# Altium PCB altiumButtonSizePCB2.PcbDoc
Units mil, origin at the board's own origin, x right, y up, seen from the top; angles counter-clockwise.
Board outline 1649.61 x 824.8 mil, 2 copper layers (Top Layer, Bottom Layer); 34 components, 33 nets, 168 pads, 45 vias.
Unrouted connection lines stored in the file: 1.
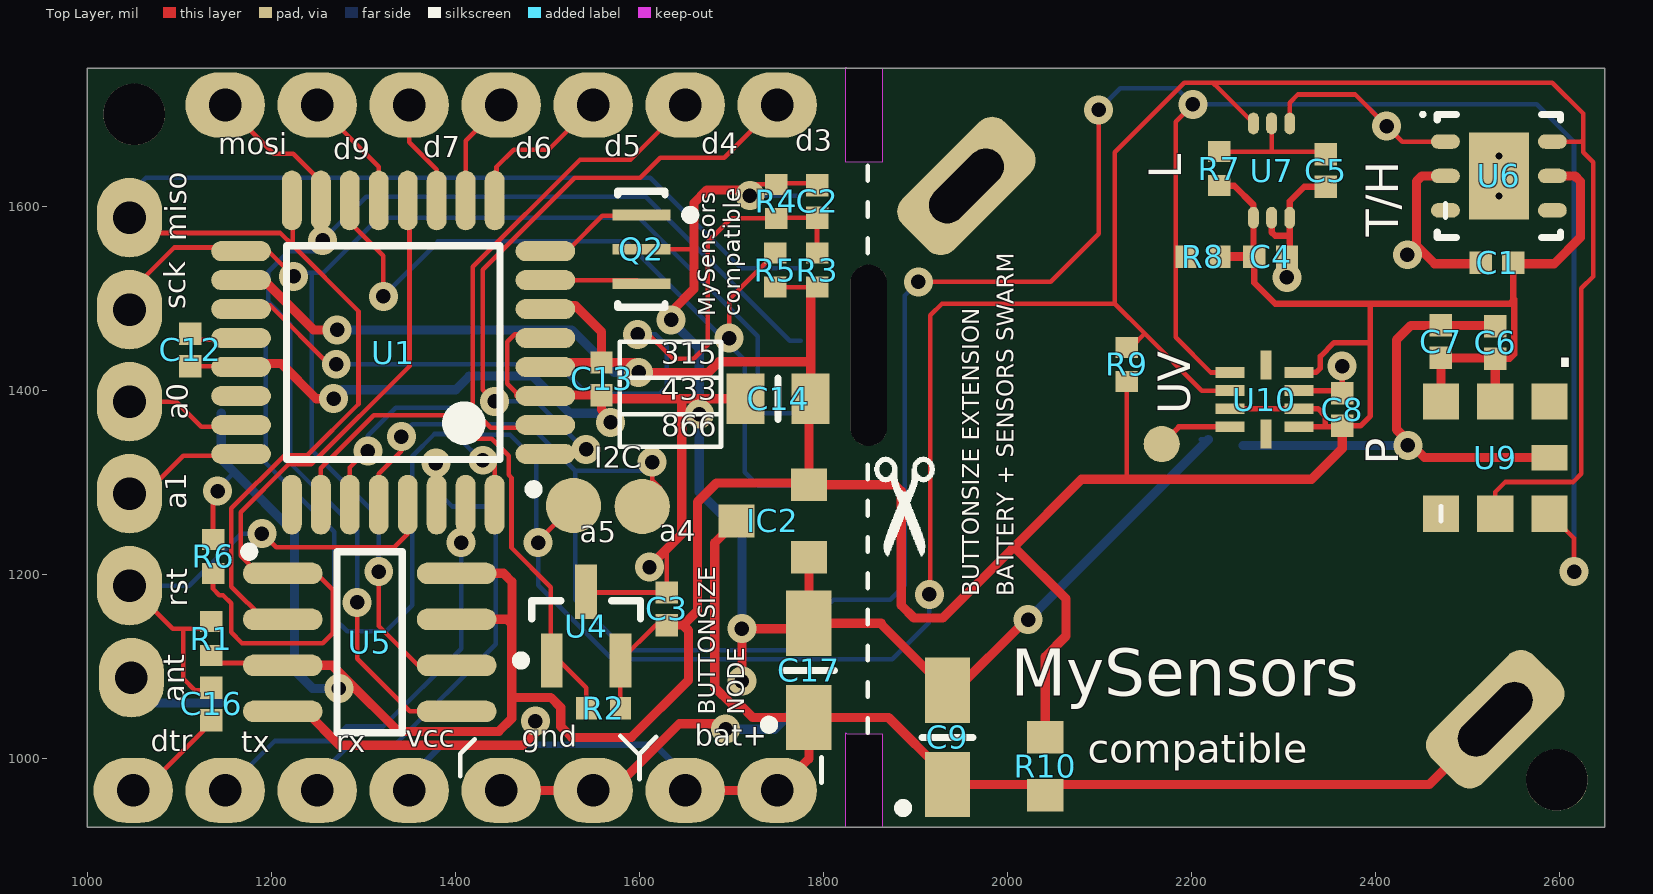
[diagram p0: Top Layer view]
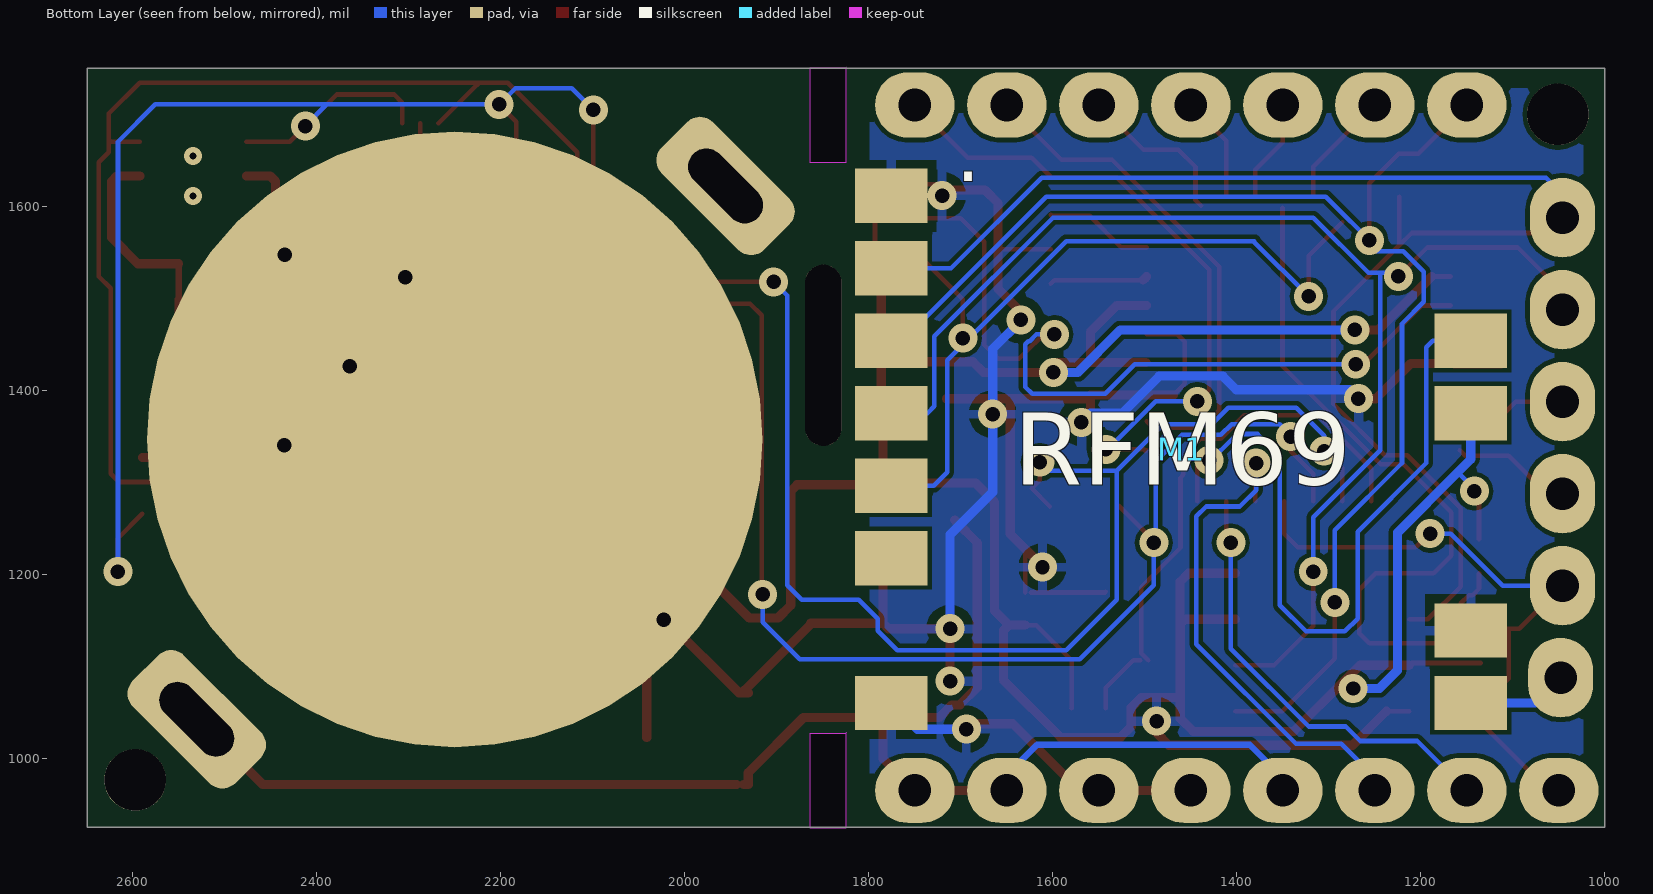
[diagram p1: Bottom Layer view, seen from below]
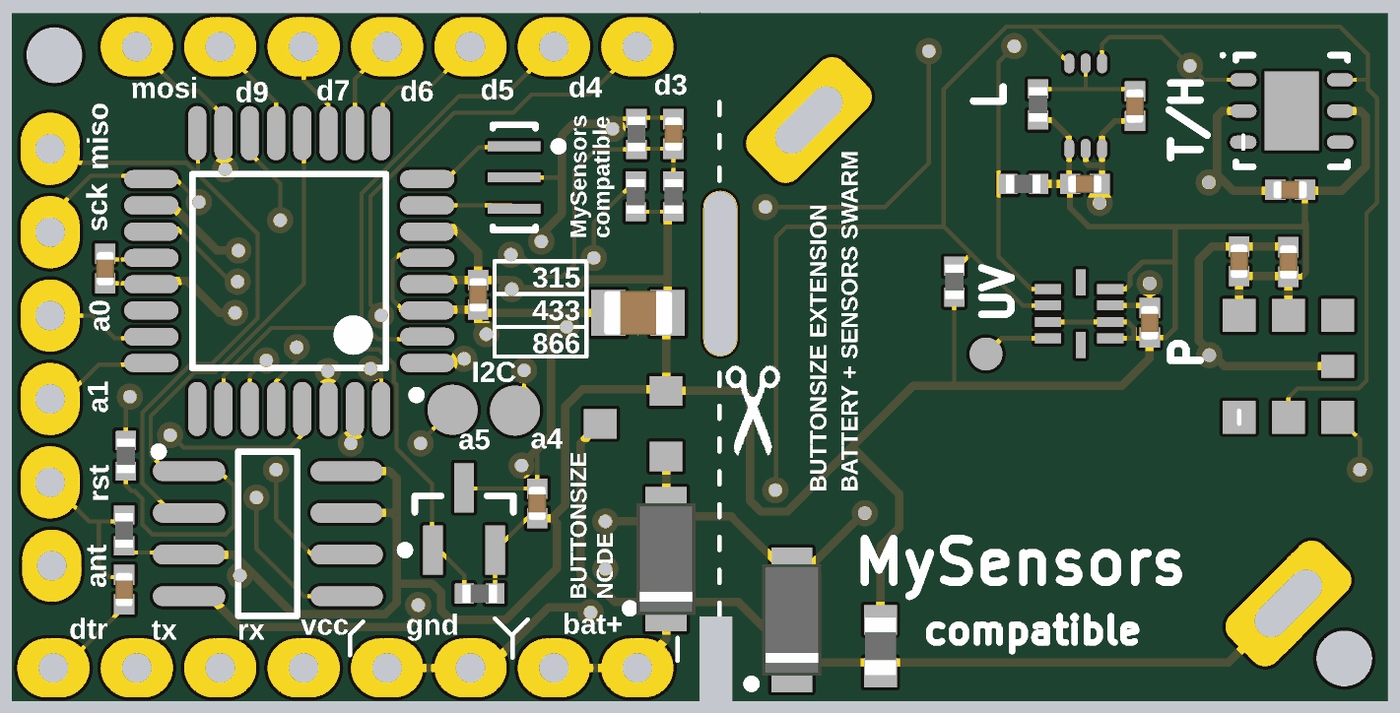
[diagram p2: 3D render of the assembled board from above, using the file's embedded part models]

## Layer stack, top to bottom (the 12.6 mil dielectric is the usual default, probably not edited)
Top Solder: solder mask 0.4, Solder Resist, Dk 3.5
Top Layer: signal copper 1.4
Dielectric 1: dielectric 12.6, FR-4, Dk 4.8
Bottom Layer: signal copper 1.4
Bottom Solder: solder mask 0.4, Solder Resist, Dk 3.5

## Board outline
1000,925.2 2649.61,925.2 2649.61,1750 1000,1750
cut-out: 1824.8,924.21 1824.8,1027.56 1825.79,1026.57 1864.17,1026.57 1864.17,924.21
cut-out: 1824.8,1647.64 1824.8,1750.98 1825.79,1750 1864.17,1750 1864.17,1647.64

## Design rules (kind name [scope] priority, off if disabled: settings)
Clearance [All] p1: gap=5
PolygonConnect [All] p1: connectstyle=Relief reliefconductorwidth=10 reliefentries=4 polygonreliefangle="90 Angle" airgapwidth=10
RoutingVias [All] p1: holewidth=15.75 width=31.5 viastyle="Through Hole" minholewidth=15.75 minwidth=31.5 maxholewidth=39.37 maxwidth=50
ShortCircuit ShortCircuit_1 [InNet('BAT+') vs InNet('VDD1')] p1: allowed=TRUE
ShortCircuit [All] p2: allowed=FALSE
SolderMaskExpansion [All] p1: expansion=4
Width [All] p1: maxlimit=10 minlimit=5 preferedwidth=5
29 further rules are at their usual default settings.

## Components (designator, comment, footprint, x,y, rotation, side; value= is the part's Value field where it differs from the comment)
C1 "100nF" CAPC1005X55N 2532.48,1538.39 r0 top
C2 "100nF" CAPC1005X55N 1793.31,1605.31 r270 top
C3 "100nF" CAPC1005X55N 1629.92,1162.4 r90 top
C4 "100nF" CAPC1005X55N 2286.42,1545.28 r180 top
C5 "100nF" CAPC1005X55N 2346.46,1638.78 r90 top
C6 "100nF" CAPC1005X55N 2530.51,1451.77 r90 top
C7 "100nF" CAPC1005X55N 2471.46,1452.76 r90 top
C8 "100nF" CAPC1005X55N 2364.17,1378.94 r270 top
C9 "47uF" CAPMP3216X180N 1935.04,1022.64 r90 top
C12 "100nF" CAPC1005X55N 1112.2,1443.9 r90 top
C13 "100nF" CAPC1005X55N 1559.06,1412.4 r90 top
C14 "4.7uF" CAPC2012X135N 1750.98,1390.75 r0 top
C16 "100nF" CAPC1005X55N 1134.84,1059.06 r270 top
C17 "47uF" CAPMP3216X180N 1784.45,1095.47 r90 top
IC2 "xc6206p332mr" XC6206 1784.45,1297.24 r270 top
M1 "rfm69hcw" rf69_rev3.0 1421.26,1335.63 r180 bottom
Q2 "CSTCE16M0V51-R0" MURA-CSTCE_V-3_V 1602.36,1553.15 r270 top
R1 "10k" RESC1005X40N 1134.84,1129.92 r90 top
R2 "100k" RESC1005X40N 1561.02,1054.13 r180 top
R3 "1M" RESC1005X40N 1793.31,1530.51 r270 top
R4 "470k" RESC1005X40N 1749.02,1605.31 r270 top
R5 "10k" RESC1005X40N 1748.03,1530.51 r270 top
R6 "10k" RESC1005X40N 1136.81,1219.49 r270 top
R7 "10k" RESC1005X40N 2230.32,1640.75 r270 top
R8 "1k" RESC1005X40N 2212.6,1545.28 r180 top
R9 "1k" RESC1005X40N 2129.92,1428.15 r90 top
R10 "0" RESC1608X55N 2041.34,991.14 r90 top
U1 "ATmega328P-AU" 32A_N 1352.36,1440.94 r180 top
U4 "ATSHA204A" 3TS1_N 1542.32,1143.7 r90 top
U5 "M25P40-VMN6TPB" MICT-MN-8_N 1307.09,1125.98 r0 top
U6 "si7020" DFN6D_N 2534.45,1632.87 r0 top
U7 "bh1750" BH1750 2287.4,1638.78 r0 top
U9 "BMP180" BMP180 2530.51,1326.77 r0 top
U10 "si1132" si1132 2281.5,1379.92 r0 top

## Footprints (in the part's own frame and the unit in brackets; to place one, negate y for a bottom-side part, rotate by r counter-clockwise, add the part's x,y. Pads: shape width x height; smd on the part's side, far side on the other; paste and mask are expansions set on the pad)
3TS1_N [mm] "SOT23, 3-Leads, Body 2.9x1.3mm, Pitch 0.95mm, Lead Span 2.4mm, IPC Medium Density"
  rect 1.5x0.6 smd: 1(-0.95,0.95) 2(-0.95,-0.95) 3(0.95,0)
  silkscreen extent -1.07,-1.5 0.7,1.92, body extent -0.7,-1.52 0.7,1.52, height 1.12
32A_N [mm] "Thin QFP, 32-Leads, Body 7x7mm, Pitch 0.8mm, IPC Medium Density"
  oval 1.65x0.55 smd: 1(-3.7,2.8) 2(-3.7,2) 3(-3.7,1.2) 4(-3.7,0.4) 5(-3.7,-0.4) 6(-3.7,-1.2) 7(-3.7,-2) 8(-3.7,-2.8) 17(4.7,-2.8) 18(4.7,-2) 19(4.7,-1.2) 20(4.7,-0.4) 21(4.7,0.4) 22(4.7,1.2) 23(4.7,2) 24(4.7,2.8)
  oval 0.55x1.65 smd: 9(-2.3,-4.2) 10(-1.5,-4.2) 11(-0.7,-4.2) 12(0.1,-4.2) 13(0.9,-4.2) 14(1.7,-4.2) 15(2.5,-4.2) 16(3.3,-4.2) 25(3.3,4.2) 26(2.5,4.2) 27(1.7,4.2) 28(0.9,4.2) 29(0.1,4.2) 30(-0.7,4.2) 31(-1.5,4.2) 32(-2.3,4.2)
  silkscreen extent -3.5,-2.95 3.45,3.9, body extent -3,-3.5 4,3.5, height 1.2
BH1750 [mm]
  oval 0.3x0.6 smd: 1(-0.5,-1.3) 2(0,-1.3) 3(0.5,-1.3) 4(0.5,1.3) 5(0,1.3) 6(-0.5,1.3)
  body extent -0.8,-1.2 0.8,1.2, height 0.75
BMP180 [mm]
  rect 1x1 smd: 1(1.5,1.55) 2(0,1.55) 3(-1.5,1.55) 4(-1.5,-1.55) 5(0,-1.55) 6(1.5,-1.55)
  rect 1x0.7 smd: 7(1.5,0)
  body extent -1.96,-1.86 1.96,1.86, height 0.93
CAPC1005X55N [mm] "Chip Capacitor, Body 1.0x0.55mm, IPC Medium Density"
  rect 0.62x0.62 smd: 1(-0.45,0) 2(0.45,0)
  body extent -0.52,-0.27 0.53,0.28, height 0.55
CAPC2012X135N [mm] "Chip Capacitor, Body 2.0x1.25mm, IPC Medium Density"
  rect 1.05x1.4 smd: 1(-0.9,0) 2(0.9,0)
  silkscreen extent 0,-0.58 0,0.58, body extent -1.05,-0.67 1.05,0.68, height 1.25
CAPMP3216X180N [mm] "Capacitor, Polarized, Molded  Body 3.2x1.6mm, IPC Medium Density"
  rect 1.8x1.25 smd: 1(-1.3,0) 2(1.3,0)
  silkscreen extent -2.07,-0.7 0,1.35, body extent -1.7,-0.9 1.7,0.9, height 1.6
DFN6D_N [mm] "SON, 6-Leads, Body 3x3mm, Pitch 0.95mm, Thermal Pad 2.4x1.65mm, IPC Medium Density"
  oval 0.8x0.4 smd: 1(-1.475,0.95) 2(-1.475,0) 3(-1.475,-0.95) 4(1.475,-0.95) 5(1.475,0) 6(1.475,0.95)
  rect 1.65x2.4 smd: 7(0,0)
  silkscreen extent -2.15,-1.7 1.7,1.75, body extent -1.55,-1.55 1.55,1.55, height 0.95
MICT-MN-8_N [mm] "SOIC, 8-Leads, Body 5x4mm, Pitch 1.27mm, IPC Medium Density"
  oval 2.2x0.6 smd: 1(-2.4,1.905) 2(-2.4,0.635) 3(-2.4,-0.635) 4(-2.4,-1.905) 5(2.4,-1.905) 6(2.4,-0.635) 7(2.4,0.635) 8(2.4,1.905)
  silkscreen extent -3.45,-2.5 0.9,2.62, body extent -2,-2.5 2,2.5, height 0.1
MURA-CSTCE_V-3_V [mm] "SMD, 3-Leads, Body 3.2x1.3mm, Pitch 0.95mm"
  rect 0.3x1.6 smd: 1(-0.95,0) 2(0,0) 3(0.95,0)
  silkscreen extent -1.6,-0.65 1.6,1.48, body extent -1.6,-0.65 1.6,0.65, height 1
RESC1005X40N [mm] "Chip Resistor, EIA 0402, Metric 1005, Body 1.0x0.5mm, IPC Medium Density"
  rect 0.58x0.62 smd: 1(-0.47,0) 2(0.47,0)
  body extent -0.52,-0.27 0.53,0.28, height 0.4
RESC1608X55N [mm] "Chip Resistor, EIA 0603, Metric 1608, Body 1.6x0.8mm, IPC Medium Density"
  rect 0.9x1 smd: 1(-0.8,0) 2(0.8,0)
  body extent -0.87,-0.47 0.88,0.48, height 0.55
rf69_rev3.0 [mm]
  rect 2x1.5 smd: 1(-9,7) 2(-9,5) 3(-9,3) 4(-9,1) 5(-9,-1) 6(-9,-3) 8(-9,-7) 9(7,-7) 10(7,-5) 13(7,1) 14(7,3)
  body extent -8.5,-7.8 6.5,7.8, height 1
si1132 [mm]
  rect 0.8x0.3 smd: 1(-1,1) 2(-1,0.5) 3(-1,0) 4(-1,-0.5) 6(0.9,-0.5) 7(0.9,0) 8(0.9,0.5) 9(0.9,1)
  rect 0.3x0.8 smd: 5(0,-0.7) 10(0,1.2)
  body extent -1.09,-0.81 1.04,1.31, height 0.65
XC6206 [mm]
  rect 0.9x1 smd: 1(1,-2) 2(2,0) 3(0,0)
  body extent -0.5,-1.75 2.5,-0.25, height 1

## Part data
C1 C2 C3 C4 C5 C6 C7 C8 C12 C13 C16: library part CC0402_100NF_16V_10%_X5R, "Non-polarised capacitor"
C9 C17: library part CTE3216-18_10UF_16V_20%_AVX_TCJ, "Polarised capacitor"
C14: library part CC0805_4.7UF_10V_10%_X5R, "Non-polarised capacitor"
IC2: library part XC6206
M1: library part rf69_rev_3.0, "rf69_rev_3.0 16mmx16mm"
Q2: library part CMP-0588-00001-1, "Ceramic Resonator, 8 MHz with Built-in Capacitance, 3.2 x 1.3 x 1 mm SMD, RoHS, Reel"
R1 R5 R6 R7 R8 R9: library part R0402_10K_1%_0.0625W_100PPM, "Resistor - 1%"
R2: library part R0402_4K7_1%_0.0625W_100PPM, "Resistor - 1%"
R3: library part R0402_1M_1%_0.0625W_100PPM, "Resistor - 1%"
R4: library part R0402_470K_1%_0.0625W_100PPM, "Resistor - 1%"
R10: library part R0603_0R_JUMPER, "Resistor"
U1: "8-bit AVR Microcontroller, 32KB Flash, 1KB EEPROM, 2KB SRAM, 32-pin TQFP, Industrial Grade (-40°C to 85°C)"
U4: library part AT88SA10HS-TSU-T, "CryptoAuthentication™ Host Security Chip, Industrial (-40 to 85 degC), 3-Pin SOT, Tape and Reel, Pb-Free"
U5: library part CMP-0357-00076-1, "4 Mb (x1) Serial NOR Flash Memory, 75 MHz, 2.3 to 3.6 V, 8-pin SO8 Narrow (MN), Tape & Reel"

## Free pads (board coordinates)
  oval 70.87x86.61 hole 35.43: 1(1046.06,1187.56) 1(1046.06,1287.56) 1(1046.06,1487.56) 1(1048.03,1087.56) A0(1046.06,1387.56) MISO(1046.06,1587.56)
  oval 86.61x70.87 hole 35.43: 2(1150,1710) 3(1250,1710) 4(1350,1710) 5(1450,1710) 6(1550,1710) 7(1650,1710) 8(1750,1710) 9(1050,965) 9(1150,965) 9(1250,965) 9(1350,965) 9(1450,965) 9(1550,965) 9(1650,965) 9(1750,965)
  round 60 smd: 10(1528.54,1274.61) 11(1603.35,1273.62)
  round 66.93 hole 66.93 unplated: 12(1051.18,1699.8) 12(2597.44,976.38)
  round 669.29 smd far side: 13(2250,1346.46)
  rrect50% 157.48x78.74 hole 39.37 slot 98.43 at 45 deg rot 45: 14(1955.71,1622.05) 14(2530.51,1042.32)
  oval 39.37x196.85 hole 39.37 slot 196.85 at 90 deg: 16(1849.41,1437.99)
  round 39.37 smd: 17(2167.98,1341.54)

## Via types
v1: diameter 31.5, hole 15.75, Top Layer to Bottom Layer, tented both sides, 43 vias
v2: diameter 19.68, hole 7.87, Top Layer to Bottom Layer, tented both sides, 2 vias

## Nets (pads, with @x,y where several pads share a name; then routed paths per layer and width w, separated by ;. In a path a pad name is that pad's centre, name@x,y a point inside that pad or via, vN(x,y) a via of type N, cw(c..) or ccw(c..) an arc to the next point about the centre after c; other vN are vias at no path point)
1132I: pad.17 U10.4 | length 81.9
  Top Layer w6: pad.17 2186.68,1360.24 U10.4
A0: pad.A0 U1.23 | length 125.2
  Top Layer w5: pad.A0 1096.69,1387.56 1124.02,1360.24 1151.57,1360.24 U1.23@1157.48,1366.14
A1: pad.1@1046.06,1287.56 U1.24 | length 130.9
  Top Layer w5: pad.1@1046.06,1287.56 1063.15,1287.56 1104.33,1328.74 1151.57,1328.74 U1.24@1157.48,1334.65
A2: U1.25
A3: R2.2 U1.26 U4.1 | length 599.1
  Top Layer w5: U1.26@1253.94,1279.53 1253.94,1315.36 1311.3,1372.72 1392.04,1372.72 1417.63,1347.13 1439.82,1347.13 1458.05,1328.9 1458.05,1308.02 1461.24,1304.84 1461.24,1228.72 1503.94,1186.02 1503.94,1114.17 U4.1@1496.06,1106.3 ; U4.1 1512.8,1106.3 1542.52,1076.57 R2.2
A4: pad.11 R8.2 U1.27 U6.1 U7.4 U9.6 U10.1 | length 3424.1
  Top Layer w5: U1.27@1285.43,1279.53 1285.43,1315.95 1303.21,1333.73 v1(1305.18,1333.73) ; pad.11 1623.03,1293.31 1614.17,1302.17 v1(1614.17,1321.85) ; v1(1903.54,1517.72) 2047.24,1517.72 2099.41,1569.88 v1(2099.41,1704.72) ; v1(2201.77,1710.63) 2183.07,1691.93 2183.07,1457.68 2221.46,1419.29 U10.1 ; U7.4 2307.09,1712.6 2315.94,1721.46 2378.15,1721.46 v1(2412.52,1687.09) 2429.33,1670.28 U6.1 ; U9.6 2616.14,1239.17 v1(2616.14,1202.76)
  Bottom Layer w5: v1(1305.18,1333.73) 1305.18,1350.46 1335.54,1380.82 1409.54,1380.82 1427.17,1363.19 1479.92,1363.19 1530.66,1312.45 ; v1(1614.17,1321.85) 1614.17,1312.89 1614.61,1312.45 1530.66,1312.45 ; v1(1903.54,1517.72) 1888.78,1502.95 1888.78,1187.99 1873.03,1172.24 1811.02,1172.24 1790.35,1151.57 1790.35,1138.61 1769.24,1117.5 1585.26,1117.5 1530.66,1172.1 1530.66,1312.45 ; v1(2099.41,1704.72) 2123.03,1728.35 2184.06,1728.35 v1(2201.77,1710.63) 2388.98,1710.63 ; v1(2412.52,1687.09) 2388.98,1710.63 ; v1(2616.14,1202.76) 2616.14,1670.28 2575.79,1710.63 2388.98,1710.63
A5: pad.10 R9.2 U1.28 U6.6 U7.6 U9.5 U10.2 | length 3001.3
  Top Layer w5: U1.28@1316.93,1279.53 1316.93,1309.06 1341.6,1333.73 v1(1341.6,1349.48) ; v1(1490.16,1234.25) 1490.16,1236.22 pad.10 ; v1(1915.45,1178.21) 1915.45,1188.09 1916.34,1188.98 1916.34,1481.3 1929.13,1494.09 2117.13,1494.09 ; R9.2 2134.65,1446.65 2149.61,1461.61 ; U10.2 2211.61,1399.61 2149.61,1461.61 ; U7.6 2230.32,1727.36 2223.43,1734.25 ; U9.5 2530.51,1289.37 2541.34,1300.2 2615.16,1300.2 2624.02,1309.06 2624.02,1510.83 2636.81,1523.62 2636.81,1647.64 2625.98,1658.46 2625.98,1672.24 ; U6.6 2624.02,1670.28 2625.98,1672.24 ; 2117.13,1494.09 2149.61,1461.61 ; 2117.13,1494.09 2117.13,1658.86 2192.52,1734.25 2223.43,1734.25 ; 2223.43,1734.25 2592.52,1734.25 2625.98,1700.79 2625.98,1672.24
  Bottom Layer w5: v1(1341.6,1349.48) 1338.58,1346.46 1336.61,1346.46 1353.35,1363.19 1405.51,1363.19 1417.32,1351.38 1459.65,1351.38 1488.19,1322.83 1488.19,1236.22 v1(1490.16,1234.25) 1490.16,1187.99 1570.65,1107.5 1875.22,1107.5 1915.45,1147.73 v1(1915.45,1178.21)
A6: C2.2 R3.1 R4.2 U1.19 | length 959.3
  Top Layer w5: U1.19@1167.32,1492.13 1198.82,1492.13 1262.73,1428.22 v1(1270.73,1428.22) ; v1(1598.43,1460.63) 1598.43,1462.6 1603.35,1467.52 1636.81,1434.06 1659.45,1434.06 1674.59,1449.19 1674.59,1561.4 1700,1586.81 R4.2 ; R4.2@1757.87,1587.8 1758.07,1587.6 C2.2 R3.1
  Bottom Layer w5: v1(1270.73,1428.22) 1510.76,1428.22 1542.93,1396.04 1622.42,1396.04 1629.92,1403.54 1629.92,1449.8 1626.59,1453.13 1625.21,1453.13 1617.71,1460.63 v1(1598.43,1460.63)
A7: U1.22
ANT: M1.9 pad.1@1048.03,1087.56 | length 109
  Bottom Layer w10: pad.1@1048.03,1087.56 1075.55,1060.04 M1.9
BAT+: C9.1 C17.1 IC2.1 pad.9@1350,965 pad.9@1650,965 pad.9@1750,965 pad.14@2530.51,1042.32 R10.1 | length 1674.3
  Top Layer w10: pad.9@1650,965 1750,965 1784.45,999.45 C17.1 ; IC2.1@1706.69,1258.86 IC2.1 1682.09,1234.25 1682.09,1076.91 1701.03,1057.97 1709.75,1057.97 1723.43,1044.29 C17.1 ; C9.1@1936.02,971.46 C9.1 1931.1,971.46 1931.1,984.25 1871.06,1044.29 C17.1 ; C9.1@1943.9,971.46 2458.66,971.46 pad.14@2529.53,1042.32
  Bottom Layer w7: pad.9@1350,965 1350,978.94 1385.83,1014.76 1617.13,1014.76 1650,981.89 1650,965 pad.9@1656.5,971.5
D0: pad.9@1250,965 U1.30 | length 555
  Top Layer w5: v1(1378.94,1320.87) 1379.92,1319.88 U1.30@1379.92,1279.53
  Bottom Layer w5: pad.9@1250,965 1250,979.33 1286.42,1015.75 1335.63,1015.75 1443.9,1124.02 1443.9,1262.8 1433.07,1273.62 1396.65,1273.62 1378.94,1291.34 v1(1378.94,1320.87)
D1: pad.9@1150,965 U1.31 | length 494.5
  Top Layer w5: v1(1406.56,1234.31) 1406.56,1236.28 1408.53,1238.25 1411.42,1235.37 U1.31@1411.42,1279.53
  Bottom Layer w5: pad.9@1155.94,965 1150,965 1203.7,1018.7 1265.75,1018.7 1281.5,1034.45 1321.85,1034.45 1406.56,1119.16 v1(1406.56,1234.31)
D2: M1.14 U1.32 | length 802.4
  Top Layer w5: v1(1430.19,1323.88) 1437.1,1323.88 1442.09,1318.9 1442.91,1319.72 U1.32@1442.91,1279.53
  Bottom Layer w5: M1.14 1187.01,1453.74 1193.9,1446.85 1193.9,1320.87 1268.7,1246.06 1268.7,1151.57 1282.48,1137.8 1324.8,1137.8 1353.35,1166.34 1353.35,1328.15 1377.56,1352.36 1399.61,1352.36 v1@1433.07,1318.9 ; v1@1430.19,1321.78 v1(1430.19,1323.88)
D3: pad.8 U1.1 | length 709.1
  Top Layer w5: v1(1442.91,1387.8) 1430.12,1400.59 1430.12,1530.84 1530.19,1630.91 1601.38,1630.91 1623.03,1652.56 1692.56,1652.56 pad.8 ; U1.1@1498.03,1334.65 1499.02,1333.66 1501.05,1335.7 v1(1542.4,1335.7)
  Bottom Layer w5: v1(1442.91,1387.8) 1488.19,1387.8 1540.29,1335.7 v1(1542.4,1335.7)
D4: pad.7 U1.2 | length 548.7
  Top Layer w5: U1.2@1498.03,1366.14 1491.14,1359.25 1438.58,1359.25 1419.29,1378.54 1419.29,1534.15 1535.73,1650.59 1590.59,1650.59 pad.7
D5: pad.6 U1.9 | length 177.8
  Top Layer w5: U1.9@1438.98,1600.39 1444.88,1606.3 1444.88,1642.72 1463.58,1661.42 1501.42,1661.42 pad.6
D6: pad.5 U1.10 | length 115.7
  Top Layer w5: U1.10@1411.42,1610.24 1411.42,1671.26 1450,1709.84 pad.5
D7: pad.4 U1.11 | length 112.2
  Top Layer w5: pad.4 1350,1669.68 1379.92,1639.76 U1.11@1379.92,1610.24
D8: R6.2 U1.12 U5.1 | length 825.8
  Top Layer w5: R6.2 1136.81,1184.06 1143.7,1177.17 1147.64,1177.17 1156.5,1168.31 1156.5,1136.81 1168.31,1125 1255.91,1125 1266.73,1135.83 1266.73,1183.07 1248.82,1200.98 U5.1 1185.83,1200.98 1166.77,1220.04 1166.77,1267.49 1218.79,1319.51 1243.72,1319.51 1350.39,1426.18 U1.12@1350.39,1598.43
D9: pad.3 U1.13 | length 127.5
  Top Layer w5: pad.3 1316.93,1643.07 U1.13@1316.93,1610.24
D10: M1.5 R5.1 U1.14 | length 871.6
  Top Layer w5: U1.14@1285.43,1582.68 1321.85,1546.26 v1(1321.85,1501.97) ; v1(1697.83,1456.69) 1697.83,1498.82 R5.1
  Bottom Layer w5: v1(1321.85,1501.97) 1380.91,1561.02 1380.91,1562.01 1585.19,1562.01 v1@1694.17,1453.03 ; v1(1697.83,1456.69) 1697.83,1449.37 1714.57,1432.64 1714.57,1311.02 1729.33,1296.26 M1.5
DTR: C16.2 pad.9@1050,965 | length 115.2
  Top Layer w5: pad.9@1050,965 1061.46,965 C16.2@1134.84,1038.39
GND: C1.1 C2.1 C3.2 C4.1 C5.1 C6.2 C7.2 C8.1 C9.2 C12.1 C13.1 C14.1 C17.2 IC2.2 M1.1 M1.8 M1.10 pad.9@1450,965 pad.9@1550,965 pad.13 Q2.2 R4.1 U1.3 U1.5 U1.21 U4.3 U5.4 U6.2 U7.2 U7.3 U9.7 U10.8 | length 4500.3
  Top Layer w5: C12.1 1164.37,1426.18 U1.21@1167.32,1429.13 ; U5.4 U5.4@1237.4,1050.98 ; U1.3@1468.9,1394.69 1456.69,1406.89 1456.69,1452.76 1464.57,1460.63 U1.5@1498.03,1460.63 ; U4.3 1543.31,1180.12 C3.2@1624.02,1180.12 ; pad.9@1550,965 pad.9@1571.3,965 ; C13.1 C13.1@1562.99,1390.75 ; v1(1568.9,1365.16) v1@1568.9,1369.09 ; Q2.2 1658.46,1553.15 1659.45,1554.13 ; v1(1611.22,1207.68) v1@1611.22,1208.66 ; C3.2 1629.92,1227.36 ; v1(1634.84,1476.38) v1@1634.84,1485.38 ; 1645.67,1390.75 1646.28,1390.14 ; v1(1665.35,1374.02) 1665.35,1390.75 ; v1(1720.28,1611.42) 1720.28,1623.82 R4.1 ; R4.1@1749.02,1624.8 C2.1@1791.54,1624.8
  Top Layer w6: U10.8 2361.22,1399.61 C8.1 v1(2364.17,1426.18)
  Top Layer w7: U7.2 2287.4,1571.85 2291.34,1567.91 2307.09,1567.91 ; C4.1@2307.09,1548.23 2307.09,1567.91 ; C5.1 2322.83,1621.06 2307.09,1605.32 U7.3 2307.09,1567.91
  Top Layer w10: U1.21@1167.32,1429.13 1210.63,1429.13 1248.95,1390.82 v1(1267.78,1390.82) ; U5.4@1237.4,1050.98 1274.21,1014.17 1473.82,1014.17 1487.28,1027.63 v1(1487.28,1040.41) ; pad.9@1450,965 pad.9@1550,965 ; U1.3@1468.9,1394.69 C13.1 1559.06,1378.94 v1@1568.9,1369.09 ; C13.1@1562.99,1390.75 1645.67,1390.75 1665.35,1390.75 C14.1 ; pad.9@1571.3,965 1643.7,1037.4 1688.13,1037.4 v1(1693.98,1031.55) ; v1@1611.22,1208.66 1646.28,1243.72 1646.28,1390.14 ; v1@1634.84,1485.38 1659.45,1509.99 1659.45,1554.13 1659.45,1603.35 1673.72,1617.62 v1@1714.07,1617.62 ; v1(1711.7,1083.71) 1711.61,1083.8 v1(1711.61,1140.75) 1778.54,1140.75 C17.2 ; IC2.2 C17.2 ; C9.2@1931.1,1070.87 1940.94,1070.87 2020.67,1150.59 v1(2022.64,1150.59) ; C9.2 1863.19,1145.67 1863.19,1146.65 C17.2 ; v1(2304.13,1522.64) C4.1 C4.1@2307.09,1548.23 ; v1(2435.04,1547.24) v1@2444.88,1557.09 ; v1(2435.53,1340.06) v1@2440.45,1340.06 ; U6.2 2450.79,1632.87 2444.88,1626.97 v1@2444.88,1557.09 ; C1.1@2514.76,1537.4 2464.57,1537.4 v1@2444.88,1557.09 ; C6.2@2529.53,1470.47 C7.2 2438.98,1470.47 2423.23,1454.72 2423.23,1357.28 v1@2440.45,1340.06 ; U9.7 2453.74,1326.77 v1@2440.45,1340.06
  Bottom Layer w5: v1@1633.86,1476.38 v1(1634.84,1476.38) ; v1(1720.28,1611.42) 1720.47,1611.22 M1.1 ; M1.8@1770.67,1055.12 M1.8 ; pad.13@2210.63,1346.46 pad.13@2218.5,1346.46
  Bottom Layer w10: v1(1267.78,1390.82) 1277.55,1400.59 1400.59,1400.59 1415.35,1415.35 1484.25,1415.35 1524.67,1374.93 1559.12,1374.93 v1(1568.9,1365.16) ; v1@1492.19,1035.49 v1@1492.19,1047.31 ; v1@1633.86,1476.38 1665.35,1444.88 v1(1665.35,1374.02) 1665.35,1289.37 1711.61,1243.11 v1(1711.61,1140.75) ; v1(1693.98,1031.55) 1747.1,1031.55 M1.8@1770.67,1055.12 ; v1@1711.61,1083.8 v1(1711.7,1083.71) ; v1(2022.64,1150.59) pad.13@2218.5,1346.46 ; pad.13@2256.4,1340.06 v1(2435.53,1340.06)
MISO: M1.2 pad.MISO U1.16 U5.2 | length 1617
  Top Layer w5: pad.MISO 1062.76,1570.87 1210.04,1570.87 1223.43,1557.48 ; U5.2 1192.28,1150.98 1156.77,1186.5 1156.77,1271.63 1214.57,1329.43 1214.57,1329.51 1239.35,1329.51 1294.9,1385.06 1294.9,1486.01 1223.43,1557.48 ; U1.16@1223.43,1610.24 1223.43,1557.48
  Bottom Layer w5: pad.MISO@1046.06,1615.94 pad.MISO 1046.06,1612.99 1063.98,1630.91 1612.2,1630.91 1710.63,1532.48 M1.2
MOSI: M1.3 pad.2 U1.15 U5.5 | length 1471.4
  Top Layer w5: pad.2 1202.93,1657.07 1223.84,1657.07 1255.9,1625 v1(1255.9,1562.99) ; v1(1293.37,1169.35) 1293.37,1108.2 1350.59,1050.98 U5.5
  Bottom Layer w5: v1@1248.03,1551.18 1219.09,1551.18 1196.85,1528.94 1196.85,1496.06 1220.47,1472.44 1220.47,1320.87 1293.37,1247.97 v1(1293.37,1169.35) ; v1@1248.03,1555.12 1303.16,1610.24 1607.28,1610.24 1763.78,1453.74 M1.3
NetC5_2: C5.2 R7.1 U7.5 | length 148
  Top Layer w5: R7.1 2287.4,1659.25 ; U7.5 2287.4,1659.25 ; C5.2 2343.7,1659.25 2287.4,1659.25
NetC12_2: C12.2 U1.20 | length 60.4
  Top Layer w5: C12.2 1119.09,1454.72 1161.42,1454.72 U1.20@1167.32,1460.63
NetQ2_1: Q2.1 U1.8 | length 119
  Top Layer w5: U1.8@1498.03,1555.12 1525.59,1555.12 1560.04,1589.57 1601.38,1589.57 Q2.1
NetQ2_3: Q2.3 U1.7 | length 111.5
  Top Layer w5: U1.7 1501.97,1519.68 1598.42,1519.68 Q2.3
  Top Layer w10: U1.7@1498.03,1523.62 U1.7@1501.97,1519.68
RST: C16.1 pad.1@1046.06,1187.56 R1.2 U1.29 | length 571.5
  Top Layer w5: pad.1@1046.06,1187.56 1093.07,1140.55 1104.33,1140.55 ; C16.1@1134.84,1073.82 1117.13,1073.82 1104.33,1086.61 1104.33,1140.55 ; R1.2@1134.84,1140.55 1104.33,1140.55 ; v1(1190.02,1244.16) 1190.88,1244.16 1205.71,1229.33 1333.66,1229.33 1348.43,1244.09 U1.29@1348.43,1279.53
  Bottom Layer w5: pad.1@1046.06,1187.56 1110.79,1187.56 1167.38,1244.16 v1(1190.02,1244.16)
SCK: M1.4 pad.1@1046.06,1487.56 U1.17 U5.6 | length 1469.1
  Top Layer w5: pad.1@1046.06,1487.56 1046.06,1506.69 1094.49,1555.12 1192.91,1555.12 v1(1224.41,1523.62) ; v1(1316.93,1202.76) 1316.93,1143.7 1359.65,1100.98 U5.6
  Bottom Layer w5: v1@1224.41,1511.81 v1(1224.41,1523.62) 1228.35,1527.56 1244.09,1527.56 ; v1(1316.93,1202.76) 1316.93,1261.81 1244.09,1334.65 1244.09,1527.56 ; M1.4 1736.22,1375 1728.72,1382.5 1728.72,1458.68 1599.81,1587.6 1316.93,1587.6 1256.89,1527.56 1244.09,1527.56
VDD1: C1.2 C3.1 C4.2 C6.1 C7.1 C8.2 C13.2 C14.2 IC2.3 M1.13 R1.1 R2.1 R3.2 R5.2 R6.1 R7.2 R8.1 R9.1 R10.2 U1.4 U1.6 U1.18 U4.2 U5.3 U5.7 U5.8 U6.5 U7.1 U9.2 U9.3 U10.3 U10.6 U10.7 U10.9 | length 5452
  Top Layer w5: R1.1@1134.84,1103.54 1210.04,1103.54 U5.3 ; R6.1 1136.81,1285.43 v1(1141.73,1290.35) ; U1.18@1167.32,1523.62 U1.18@1187.99,1523.62 ; v1(1273.62,1075.79) 1274.61,1075.79 v1@1282.97,1084.15 ; U1.4@1498.03,1429.13 U1.4@1499.02,1430.12 ; R2.1@1579.72,1054.33 R2.1 1579.53,1106.1 U4.2 1618.11,1144.69 C3.1 ; R5.2 R3.2 R3.2@1786.42,1505.12 ; IC2.3@1782.48,1299.21 IC2.3 ; C14.2@1784.45,1388.78 C14.2 ; 2129.92,1304.13 R9.1
  Top Layer w6: 2005.36,1227.8 2009.4,1227.8 ; U10.3 U10.7 2337.6,1379.92 2345.47,1372.05 2345.47,1360.24 ; U10.6 2363.19,1360.24 C8.2 2383.86,1361.22 2394.68,1372.05 2394.68,1451.77 ; U10.9 2335.63,1419.29 2340.43,1424.09 2340.43,1436.88 2355.32,1451.77 2394.68,1451.77 ; 2394.68,1493.11 2394.68,1451.77
  Top Layer w7: R7.2 2246.85,1622.24 2267.72,1601.38 U7.1 C4.2@2267.72,1546.26 ; C4.2 2268.7,1516.73 2291.34,1494.09 2546.33,1494.09 2551.22,1498.98 2551.22,1439.01 2546.26,1434.06 C6.1 ; 2550.2,1500 2550.2,1537.4 C1.2
  Top Layer w10: U1.18@1187.99,1523.62 1246.06,1465.55 v1(1271.65,1465.55) ; U5.3 1266.14,1100.98 v1@1282.48,1084.65 ; v1@1282.97,1084.15 1337.95,1029.17 1447.48,1029.17 1461.46,1043.15 1461.46,1065.94 ; U5.7 1456.3,1150.98 1461.61,1145.67 ; U5.8 1452.56,1200.98 1461.61,1191.93 1461.61,1145.67 ; U1.6@1498.03,1492.13 1530.51,1492.13 1559.06,1463.58 C13.2 ; U1.4@1499.02,1430.12 C13.2 ; v1@1595.47,1430.12 C13.2 ; v1(1599.41,1419.29) 1675.2,1419.29 1686.85,1430.94 1785.59,1430.94 1786.42,1430.12 ; C3.1 1647.64,1144.69 ; IC2.3@1782.48,1299.21 1684.06,1299.21 1663.39,1278.54 1663.39,1160.43 1647.64,1144.69 ; C14.2@1784.45,1388.78 IC2.3 1877.95,1297.24 1884.84,1290.35 1884.84,1166.34 1898.73,1152.46 1930.02,1152.46 2005.36,1227.8 2080.71,1303.15 2130.91,1303.15 ; C14.2 1786.42,1430.12 ; R3.2@1786.42,1505.12 1786.42,1430.12 ; 2009.4,1227.8 2063.98,1173.23 2063.98,1132.87 2041.34,1110.24 R10.2 ; 2129.92,1304.13 2130.91,1303.15 ; R8.1 C4.2 C4.2@2267.72,1546.26 ; C8.2 2364.17,1336.61 2330.71,1303.15 2130.91,1303.15 ; U9.3 C7.1 2529.53,1435.04 C6.1 U9.2 ; C1.2@2550.2,1537.4 2594.49,1537.4 2623.03,1565.94 2623.03,1626.97 2617.13,1632.87 U6.5 ; 1461.46,1065.94 1461.46,1145.51 1461.61,1145.67 ; 1461.46,1065.94 1461.66,1066.15 1503.73,1066.15 1514.76,1055.12 1514.76,1034.45 1526.57,1022.64 1591.54,1022.64 1653.54,1084.65 1653.54,1138.78 1647.64,1144.69
  Bottom Layer w5: v1(1141.73,1290.35) 1141.73,1292.91 1159.71,1310.88
  Bottom Layer w10: M1.13 1145.67,1324.92 1159.71,1310.88 1225.39,1245.19 1225.39,1095.47 1245.08,1075.79 v1(1273.62,1075.79) ; v1(1271.65,1465.55) 1526.57,1465.55 1572.83,1419.29 v1(1599.41,1419.29)
pads on no net: M1.6 U6.3 U6.4 U6.7 U9.1 U9.4 U10.5 U10.10
copper on no net:
  other v2: 2534.45,1611.22 2534.45,1654.53

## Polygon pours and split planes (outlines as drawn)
GND on Bottom Layer "Bottom Overlay-No Net" (solid, pour order 0): 1023.62,1728.35 1023.62,944.88 1803.15,944.88 1799.21,948.82 1799.21,1728.35

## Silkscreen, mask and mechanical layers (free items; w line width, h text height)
Top Overlay:
  drawing of 29 lines, arcs and shapes, not listed
  text "d3" at 1769.68,1652.56 h39.37
  text "d4" at 1667.32,1649.61 h39.37
  text "mosi" at 1142.72,1648.62 h39.37
  text "d5" at 1562.01,1646.65 h39.37
  text "d7" at 1365.16,1645.67 h39.37
  text "d6" at 1465.55,1644.68 h39.37
  text "d9" at 1267.72,1643.7 h39.37
  text "L" at 2188.98,1629.92 h35.43 r90
  text "T/H" at 2425.2,1566.93 h35.43 r90
  text "miso" at 1115.16,1562.01 h39.37 r90
  text "sck" at 1114.17,1488.19 h39.37 r90
  text "MySensors" at 1688.98,1480.31 h31.5 r90
  text "compatible" at 1716.54,1480.31 h31.5 r90
  text "315" at 1624.02,1421.26 h39.37
  text "433" at 1624.02,1381.89 h39.37
  text "UV" at 2198.82,1374.02 h35.43 r90
  text "a0" at 1117.13,1368.11 h39.37 r90
  text "866" at 1624.02,1342.52 h39.37
  text "P" at 2425.2,1318.9 h35.43 r90
  text "I2C" at 1551.18,1308.07 h39.37
  text "a1" at 1115.16,1270.67 h39.37 r90
  text "a4" at 1622.05,1228.35 h39.37
  text "a5" at 1535.43,1227.36 h39.37
  text "BUTTONSIZE EXTENSION" at 1976.38,1176.18 h31.5 r90
  text "BATTERY + SENSORS SWARM" at 2013.78,1176.18 h31.5 r90
  text "rst" at 1116.14,1164.37 h39.37 r90
  text "MySensors" at 2003.94,1067.91 h51.18
  text "ant" at 1113.19,1061.02 h39.37 r90
  text "BUTTONSIZE" at 1688.98,1047.24 h31.5 r90
  text "NODE" at 1720.47,1047.24 h31.5 r90
  text "bat+" at 1660.43,1005.91 h39.37
  text "vcc" at 1346.46,1004.92 h39.37
  text "gnd" at 1472.44,1004.92 h39.37
  text "dtr" at 1068.9,1000 h39.37
  text "tx" at 1167.32,999.02 h39.37
  text "rx" at 1270.67,999.02 h39.37
  text "compatible" at 2087.6,995.08 h31.5
Bottom Overlay:
  text "RFM69" at 1642.72,1297.24 h78.74
Mechanical 1:
  lines w5.04: 1000,925.2 1824.8,925.2 1824.8,1026.57 1864.17,1026.57 1864.17,925.19 2649.61,925.19 2649.61,1749.02 1864.17,1749.02 1864.17,1647.64 1824.8,1647.64 1824.8,1750 1000,1750 1000,925.2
